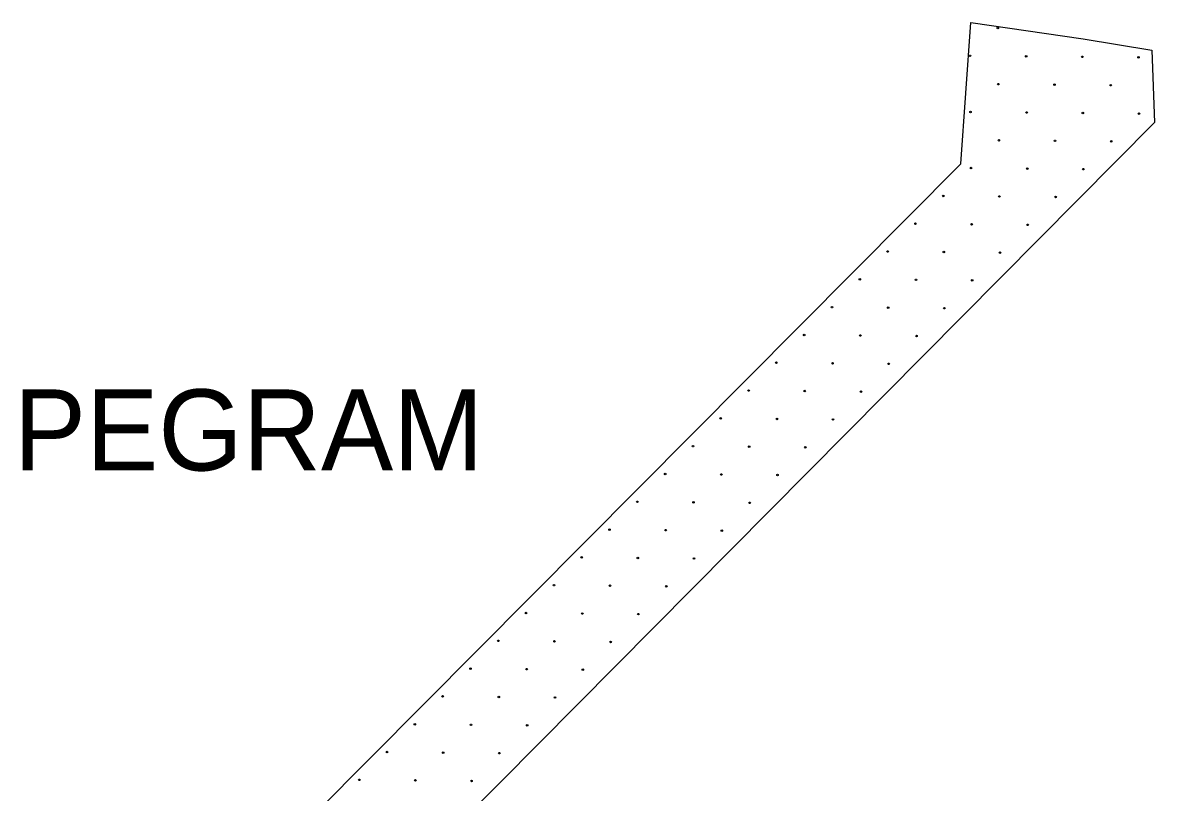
# Model space of a CAD drawing. Extents: x 1612280 to 1883141, y 560852 to 780851.
# Drawn here: x 1659042 to 1666791, y 643239 to 648509 of the extents above; entities that cross this region are included whole.
import ezdxf

# ---------------------------------------------------------------- set-up
doc = ezdxf.new("R2010")
doc.units = 0
for name, color, linetype in [('DESIGN - EROSION CONTROL - Devices', 7, 'Continuous'), ('DESIGN - SCRATCH - User 1', 7, 'Continuous'), ('SURVEY - VEGETATION - Features with Text', 7, 'Continuous')]:
    doc.layers.add(name, color=color, linetype=linetype)

msp = doc.modelspace()

# ---------------------------------------------------------------- linework, layer by layer
at = {"layer": 'DESIGN - EROSION CONTROL - Devices'}
for centre in [(1665718.8, 648473), (1665718.8, 648473), (1665528.3, 648282.5), (1665528.3, 648282.5), (1665912.9, 648278.8), (1665912.9, 648278.8), (1666297.4, 648275.1), (1666297.4, 648275.1), (1666682, 648271.3), (1666682, 648271.3), (1665722.5, 648088.4), (1665722.5, 648088.4), (1666107, 648084.7), (1666107, 648084.7), (1666491.6, 648080.9), (1666491.6, 648080.9), (1665532.1, 647898), (1665532.1, 647898), (1665916.6, 647894.3), (1665916.6, 647894.3), (1666301.2, 647890.5), (1666301.2, 647890.5), (1666685.7, 647886.8), (1666685.7, 647886.8), (1665726.2, 647703.9), (1665726.2, 647703.9), (1666110.8, 647700.1), (1666110.8, 647700.1), (1666495.3, 647696.4), (1666495.3, 647696.4), (1665535.8, 647513.4), (1665535.8, 647513.4), (1665920.4, 647509.7), (1665920.4, 647509.7), (1666304.9, 647506), (1666304.9, 647506), (1665345.4, 647323), (1665345.4, 647323), (1665730, 647319.3), (1665730, 647319.3), (1666114.5, 647315.6), (1666114.5, 647315.6), (1665155, 647132.6), (1665155, 647132.6), (1665539.5, 647128.9), (1665539.5, 647128.9), (1665924.1, 647125.2), (1665924.1, 647125.2), (1664964.6, 646942.2), (1664964.6, 646942.2), (1665349.1, 646938.5), (1665349.1, 646938.5), (1665733.7, 646934.7), (1665733.7, 646934.7), (1664774.2, 646751.8), (1664774.2, 646751.8), (1665158.7, 646748.1), (1665158.7, 646748.1), (1665543.3, 646744.3), (1665543.3, 646744.3), (1664583.8, 646561.4), (1664583.8, 646561.4), (1664968.3, 646557.7), (1664968.3, 646557.7), (1665352.9, 646553.9), (1665352.9, 646553.9), (1664393.4, 646371), (1664393.4, 646371), (1664777.9, 646367.3), (1664777.9, 646367.3), (1665162.5, 646363.5), (1665162.5, 646363.5), (1664202.9, 646180.6), (1664202.9, 646180.6), (1664587.5, 646176.8), (1664587.5, 646176.8), (1664972, 646173.1), (1664972, 646173.1), (1664012.5, 645990.2), (1664012.5, 645990.2), (1664397.1, 645986.4), (1664397.1, 645986.4), (1664781.6, 645982.7), (1664781.6, 645982.7), (1663822.1, 645799.8), (1663822.1, 645799.8), (1664206.7, 645796), (1664206.7, 645796), (1664591.2, 645792.3), (1664591.2, 645792.3), (1663631.7, 645609.3), (1663631.7, 645609.3), (1664016.3, 645605.6), (1664016.3, 645605.6), (1664400.8, 645601.9), (1664400.8, 645601.9), (1663441.3, 645418.9), (1663441.3, 645418.9), (1663825.9, 645415.2), (1663825.9, 645415.2), (1664210.4, 645411.5), (1664210.4, 645411.5), (1663250.9, 645228.5), (1663250.9, 645228.5), (1663635.4, 645224.8), (1663635.4, 645224.8), (1664020, 645221.1), (1664020, 645221.1), (1663060.5, 645038.1), (1663060.5, 645038.1), (1663445, 645034.4), (1663445, 645034.4), (1663829.6, 645030.6), (1663829.6, 645030.6), (1662870.1, 644847.7), (1662870.1, 644847.7), (1663254.6, 644844), (1663254.6, 644844), (1663639.2, 644840.2), (1663639.2, 644840.2), (1662679.7, 644657.3), (1662679.7, 644657.3), (1663064.2, 644653.6), (1663064.2, 644653.6), (1663448.8, 644649.8), (1663448.8, 644649.8), (1662489.3, 644466.9), (1662489.3, 644466.9), (1662873.8, 644463.2), (1662873.8, 644463.2), (1663258.4, 644459.4), (1663258.4, 644459.4), (1662298.8, 644276.5), (1662298.8, 644276.5), (1662683.4, 644272.7), (1662683.4, 644272.7), (1663068, 644269), (1663068, 644269), (1662108.4, 644086.1), (1662108.4, 644086.1), (1662493, 644082.3), (1662493, 644082.3), (1662877.5, 644078.6), (1662877.5, 644078.6), (1661918, 643895.7), (1661918, 643895.7), (1662302.6, 643891.9), (1662302.6, 643891.9), (1662687.1, 643888.2), (1662687.1, 643888.2), (1661727.6, 643705.2), (1661727.6, 643705.2), (1662112.2, 643701.5), (1662112.2, 643701.5), (1662496.7, 643697.8), (1662496.7, 643697.8), (1661537.2, 643514.8), (1661537.2, 643514.8), (1661921.8, 643511.1), (1661921.8, 643511.1), (1662306.3, 643507.4), (1662306.3, 643507.4), (1661346.8, 643324.4), (1661346.8, 643324.4), (1661731.3, 643320.7), (1661731.3, 643320.7), (1662115.9, 643317), (1662115.9, 643317)]:
    msp.add_circle(centre, 5.28, dxfattribs=at)
at = {"layer": 'DESIGN - SCRATCH - User 1'}
for points in [[(1660487.6, 639279.2), (1661029.3, 638832.6), (1661684.8, 638980.3), (1661729.5, 638981.1), (1661728.3, 639088.7), (1660835.9, 639266.7), (1661051.2, 643100.5), (1665466.1, 647542.7), (1665535.1, 648509.4), (1666303.1, 648398.2)], [(1660487.6, 639279.2), (1661029.3, 638832.6), (1661684.8, 638980.3), (1661729.5, 638981.1), (1661728.3, 639088.7), (1660835.9, 639266.7), (1661051.2, 643100.5), (1665466.1, 647542.7), (1665535.1, 648509.4), (1666303.1, 648398.2)], [(1666303.1, 648398.2), (1666772.4, 648319.9), (1666790.7, 647824.7), (1661784, 642774.5), (1661621.2, 639874.8), (1662471.3, 639705.2), (1662483.6, 638623), (1662446.9, 638451.9), (1662312.5, 638305.1), (1662117, 638237.9), (1661774.9, 638231.7), (1660659.5, 638776), (1660518.3, 638566.2), (1660768.5, 638391.5), (1661009.2, 638219.4), (1661337.8, 638085.6), (1661490.6, 638035.9), (1661454.1, 637510.3), (1660485.5, 638308.9)], [(1666303.1, 648398.2), (1666772.4, 648319.9), (1666790.7, 647824.7), (1661784, 642774.5), (1661621.2, 639874.8), (1662471.3, 639705.2), (1662483.6, 638623), (1662446.9, 638451.9), (1662312.5, 638305.1), (1662117, 638237.9), (1661774.9, 638231.7), (1660659.5, 638776), (1660518.3, 638566.2), (1660768.5, 638391.5), (1661009.2, 638219.4), (1661337.8, 638085.6), (1661490.6, 638035.9), (1661454.1, 637510.3), (1660485.5, 638308.9)]]:
    msp.add_lwpolyline(points, dxfattribs=at)

# ---------------------------------------------------------------- texts
at = {"layer": 'SURVEY - VEGETATION - Features with Text'}
msp.add_text('PEGRAM', height=554.99, rotation=0.00003, dxfattribs=at).set_placement((1658981.5, 645442.9))
msp.add_text('PEGRAM', height=554.99, rotation=0.00003, dxfattribs=at).set_placement((1658981.5, 645442.9))

doc.saveas('drawing.dxf')
